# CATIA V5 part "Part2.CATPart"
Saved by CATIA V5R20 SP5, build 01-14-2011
Part number: 螺母
Bounding box of the stored display mesh (mm): x -56.939 to 56.939, y -49.401 to 49.401, z 0 to 30
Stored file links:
  E:\180522132\3.8卡瓦\Part2.CATPart
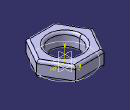
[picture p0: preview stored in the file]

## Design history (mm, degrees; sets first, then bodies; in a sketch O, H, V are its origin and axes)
Body1 (main body)
  Sketch1 on xy-plane, origin (0, 0, 0), H (1, 0, 0), V (0, 1, 0)
    point P1 (28.6269, -49.2193)
    point P2 (56.9387, 0.182)
    point P3 (28.3117, 49.4013)
    point P4 (-28.6269, 49.2193)
    point P5 (-56.9387, -0.182)
    point P6 (-28.3117, -49.4013)
    point P7 (42.7828, -24.5187)
    line L1 (28.6269, -49.2193) -> (56.9387, 0.182)
    line L2 (56.9387, 0.182) -> (28.3117, 49.4013)
    line L3 (28.3117, 49.4013) -> (-28.6269, 49.2193)
    line L4 (-28.6269, 49.2193) -> (-56.9387, -0.182)
    line L5 (-56.9387, -0.182) -> (-28.3117, -49.4013)
    line L6 (-28.3117, -49.4013) -> (28.6269, -49.2193)
    construction line L7 (0, 0) -> (42.7828, -24.5187)
    construction circle A1 centre (0, 0) radius 56.9389
    construction arc A2 centre (-56.9387, -0.182) radius 56.9389 from (-28.6269, 49.2193) to (-28.3117, -49.4013) cw
    construction arc A3 centre (56.9387, 0.182) radius 56.9389 from (28.3117, 49.4013) to (28.6269, -49.2193) ccw
    circle A4 centre (0, 0) radius 29.5761
    coincidence: A1 P1, A1 P2, A1 P3, A1 P4, A1 P5, A1 P6, A2 O, A3 O
    midpoint: P7 L1
    parallelism: L1 L4
  Pad1: profile Sketch1, direction (0, 0, 1), length 30
  Sketch2 on yz-plane, origin (0, 0, 0), H (0, 1, 0), V (0, 0, 1)
    point P1 (25.182, 30)
    reference projected point E1 (0.182, 30) from vertex [face of Pad1 from Sketch1.L2 | end face of Pad1 | face of Pad1 from Sketch1.L1]
    distance P1 E1 = 25
  Sketch3 on xy-plane, origin (0, 0, 0), H (1, 0, 0), V (0, 1, 0)
    circle A1 centre (0, 0) radius 49.2719
  Sketch4 on yz-plane, origin (0, 0, 0), H (0, 1, 0), V (0, 0, 1)
  Sketch5 on yz-plane, origin (0, 0, 0), H (0, 1, 0), V (0, 0, 1)
  Fillet1: radius 5, on end face of Pad1
  Fillet2: radius 5, on start face of Pad1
